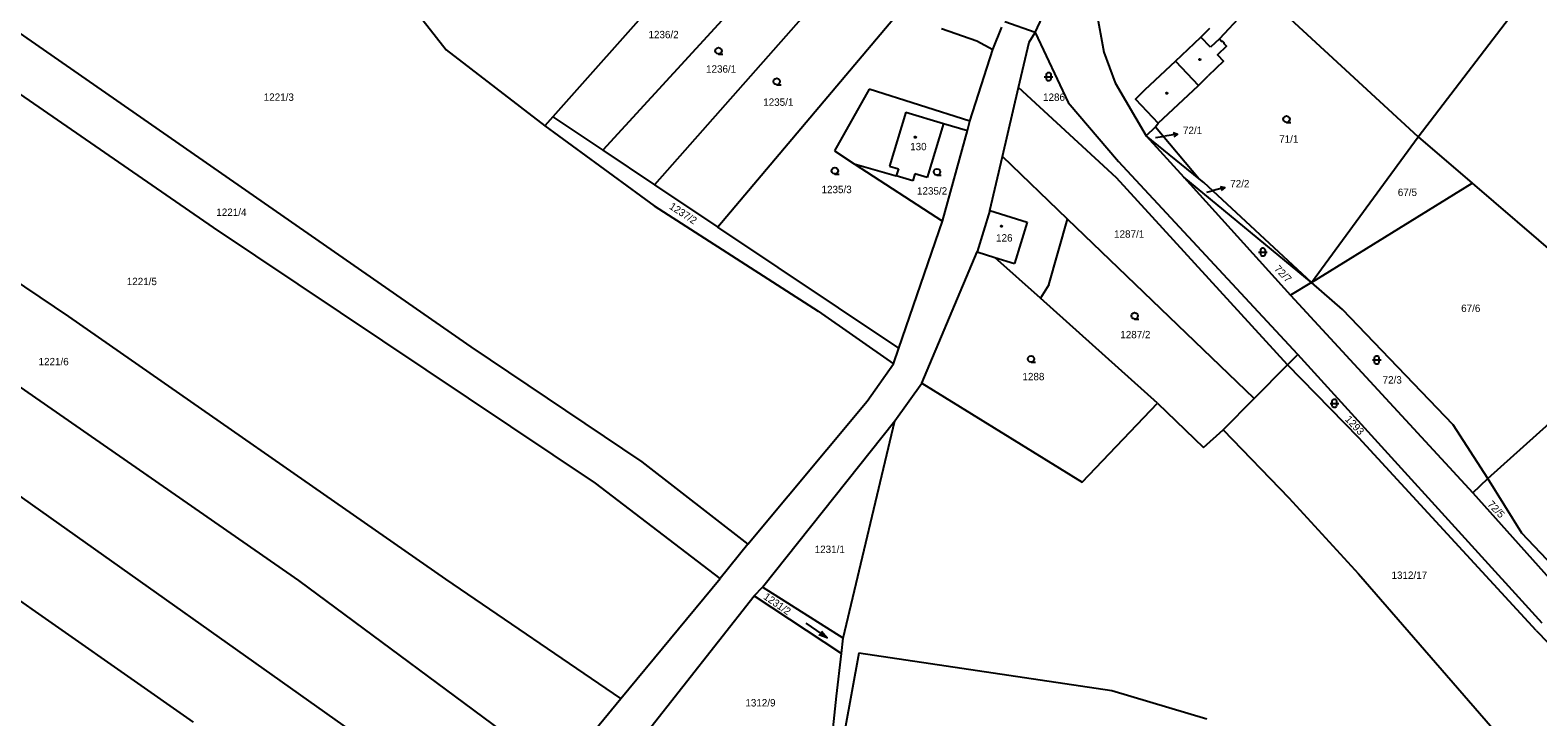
# Model space of a CAD drawing. Extents: x -799786 to -795190, y -1021716 to -1017834.
# Drawn here: x -798278.5 to -797930.9, y -1019350.1 to -1019191.9 of the extents above; entities that cross this region are included whole.
import ezdxf

# ---------------------------------------------------------------- set-up
doc = ezdxf.new("R2010")
doc.units = 0
for name, color, linetype in [('Default', 7, 'Continuous'), ('KN_HRANICE', 7, 'Continuous'), ('KN_KULTURY', 7, 'Continuous'), ('KN_PARCELY', 7, 'Continuous'), ('KN_SLUCKY', 7, 'Continuous')]:
    doc.layers.add(name, color=color, linetype=linetype)

# ---------------------------------------------------------------- blocks, each defined once
blk = doc.blocks.new('304')
at = {"layer": 'Default'}
blk.add_lwpolyline([(0, 0), (-0.38, 0.1), (-0.65, 0.37), (-0.75, 0.74), (-0.65, 1.11), (-0.38, 1.38), (-0.01, 1.48), (0.36, 1.38), (0.63, 1.11), (0.73, 0.73), (0.63, 0.35), (0.36, 0.08), (-0.02, -0.02), (0.98, -0.02)], dxfattribs=at)
blk = doc.blocks.new('316')
at = {"layer": 'Default'}
for points in [[(-1, 1), (0.27, 1), (1, 1)], [(-0.5, 1.5), (-0.4, 1.79), (-0.15, 1.97), (0.16, 1.97), (0.41, 1.79), (0.51, 1.5), (0.51, 0.5), (0.41, 0.21), (0.16, 0.03), (-0.15, 0.03), (-0.4, 0.21), (-0.5, 0.5), (-0.5, 1.5)]]:
    blk.add_lwpolyline(points, dxfattribs=at)
blk = doc.blocks.new('802')
at = {"layer": 'Default'}
blk.add_line((-3, 0), (3, 0), dxfattribs=at)
blk.add_lwpolyline([(1, 0.5), (3, 0), (1, -0.5)], dxfattribs=at)
blk = doc.blocks.new('10292')
at = {"layer": 'Default'}
blk.add_line((0, 3), (0, 0), dxfattribs=at)
blk.add_lwpolyline([(-0.5, 2), (0, 3), (0.5, 2)], dxfattribs=at)
blk = doc.blocks.new('402')
at = {"layer": 'Default'}
blk.add_lwpolyline([(0.09, 0.15), (0.18, 0), (0.09, -0.15), (-0.09, -0.15), (-0.18, 0), (-0.09, 0.15), (0.09, 0.15)], dxfattribs=at)

msp = doc.modelspace()

# ---------------------------------------------------------------- linework, layer by layer
at = {"layer": 'KN_HRANICE'}
for p, q in [((-798347.52, -1019146.35), (-798176.91, -1019264.88)), ((-797958.45, -1019216.47), (-797917.67, -1019163.19)), ((-798119.98, -1019168.95), (-798158.02, -1019211.88)), ((-798106.25, -1019175.74), (-798146.5, -1019219.57)), ((-798046.82, -1019192.47), (-798040.29, -1019178.61)), ((-798093.94, -1019181.55), (-798134.55, -1019227.54)), ((-798190.13, -1019186.83), (-798182.57, -1019196.42)), ((-798078.38, -1019188.04), (-798119.93, -1019237.3)), ((-798032.69, -1019187.31), (-798030.99, -1019196.93)), ((-797999, -1019188.24), (-798004.3, -1019193.91)), ((-797958.45, -1019216.47), (-797988.89, -1019188.44)), ((-798068.37, -1019191.52), (-798060.24, -1019194.35)), ((-798056.57, -1019196.32), (-798054.49, -1019191.2)), ((-798046.82, -1019192.47), (-798053.76, -1019189.97)), ((-798048.16, -1019194.68), (-798046.82, -1019192.47)), ((-798046.82, -1019192.47), (-798039.2, -1019208.59)), ((-798008.6, -1019193.51), (-798006.49, -1019191.45)), ((-798060.24, -1019194.35), (-798056.57, -1019196.32)), ((-798050.59, -1019205.12), (-798048.16, -1019194.68)), ((-798006.34, -1019195.81), (-798008.6, -1019193.51)), ((-798004.3, -1019193.91), (-798006.34, -1019195.81)), ((-798269.58, -1019257.87), (-798358.17, -1019198.54)), ((-798236.26, -1019237.37), (-798295.35, -1019196.67)), ((-798182.57, -1019196.42), (-798159.84, -1019213.93)), ((-798061.82, -1019212.89), (-798056.57, -1019196.32)), ((-798030.99, -1019196.93), (-798028.35, -1019204)), ((-798009.16, -1019204.63), (-798006.89, -1019202.42)), ((-798085.07, -1019205.49), (-798093.09, -1019219.72)), ((-798061.82, -1019212.89), (-798085.07, -1019205.49)), ((-798054.32, -1019221.03), (-798050.59, -1019205.12)), ((-798028.06, -1019225.96), (-798050.59, -1019205.12)), ((-798028.35, -1019204), (-798021.19, -1019216.24)), ((-798018.42, -1019213.3), (-798009.16, -1019204.63)), ((-798039.2, -1019208.59), (-798027.56, -1019222.16)), ((-798158.02, -1019211.88), (-798159.84, -1019213.93)), ((-798158.02, -1019211.88), (-798146.5, -1019219.57)), ((-798067.95, -1019213.37), (-798071.72, -1019225.83)), ((-798067.95, -1019213.37), (-798062.4, -1019215)), ((-798062.4, -1019215), (-798061.82, -1019212.89)), ((-798019.05, -1019214.21), (-798018.42, -1019213.3)), ((-798159.84, -1019213.93), (-798134.6, -1019232.4)), ((-798068.14, -1019235.94), (-798062.4, -1019215)), ((-798021.19, -1019216.24), (-798019.05, -1019214.21)), ((-798021.19, -1019216.24), (-798012.54, -1019225.79)), ((-798008.94, -1019226.16), (-798021.19, -1019216.24)), ((-798019.05, -1019214.21), (-798008.94, -1019226.16)), ((-797983.09, -1019250.06), (-797958.45, -1019216.47)), ((-797958.45, -1019216.47), (-797946.01, -1019227.17)), ((-798146.5, -1019219.57), (-798134.55, -1019227.54)), ((-798093.09, -1019219.72), (-798088.51, -1019222.7)), ((-798088.51, -1019222.7), (-798068.14, -1019235.94)), ((-798088.51, -1019222.7), (-798078.8, -1019225.46)), ((-798057.23, -1019233.47), (-798054.32, -1019221.03)), ((-798039.31, -1019235.46), (-798054.32, -1019221.03)), ((-797986.2, -1019266.62), (-798027.56, -1019222.16)), ((-798134.55, -1019227.54), (-798119.93, -1019237.3)), ((-798074.98, -1019226.61), (-798078.8, -1019225.46)), ((-798074.5, -1019224.99), (-798074.98, -1019226.61)), ((-798071.72, -1019225.83), (-798074.5, -1019224.99)), ((-797988.61, -1019269.05), (-798028.06, -1019225.96)), ((-798012.54, -1019225.79), (-797987.94, -1019252.98)), ((-797983.09, -1019250.06), (-798012.54, -1019225.79)), ((-798007.89, -1019227.01), (-798008.94, -1019226.16)), ((-797983.09, -1019250.06), (-798007.89, -1019227.01)), ((-797983.09, -1019250.06), (-797946.01, -1019227.17)), ((-797946.01, -1019227.17), (-797925.82, -1019244.54)), ((-798134.6, -1019232.4), (-798096.79, -1019256.67)), ((-798057.23, -1019233.47), (-798060.19, -1019242.98)), ((-798148.19, -1019296.29), (-798236.26, -1019237.37)), ((-798078.19, -1019265.16), (-798119.93, -1019237.3)), ((-798078.19, -1019265.16), (-798068.14, -1019235.94)), ((-798043.66, -1019250.61), (-798039.31, -1019235.46)), ((-797996.29, -1019276.8), (-798039.31, -1019235.46)), ((-798323.08, -1019244.85), (-798216.61, -1019318.7)), ((-798072.89, -1019273.22), (-798060.19, -1019242.98)), ((-798060.19, -1019242.98), (-798056.11, -1019244.26)), ((-798045.59, -1019253.66), (-798056.11, -1019244.26)), ((-798385.05, -1019250.48), (-798240.9, -1019351.36)), ((-798043.66, -1019250.61), (-798045.59, -1019253.66)), ((-797983.09, -1019250.06), (-797987.94, -1019252.98)), ((-797975.96, -1019256.3), (-797983.09, -1019250.06)), ((-798018.55, -1019277.83), (-798045.59, -1019253.66)), ((-797987.94, -1019252.98), (-797945.88, -1019298.52)), ((-798182.69, -1019318.4), (-798269.58, -1019257.87)), ((-798096.79, -1019256.67), (-798079.43, -1019268.77)), ((-797950.44, -1019282.82), (-797975.96, -1019256.3)), ((-797942.42, -1019295.21), (-797904.34, -1019261.03)), ((-798176.91, -1019264.88), (-798137.44, -1019291.33)), ((-798079.43, -1019268.77), (-798078.19, -1019265.16)), ((-798085.54, -1019277.41), (-798079.43, -1019268.77)), ((-797996.29, -1019276.8), (-797988.61, -1019269.05)), ((-797988.61, -1019269.05), (-797986.2, -1019266.62)), ((-797972.19, -1019285.87), (-797988.61, -1019269.05)), ((-797929.91, -1019328.57), (-797986.2, -1019266.62)), ((-798079.13, -1019281.89), (-798072.89, -1019273.22)), ((-798072.89, -1019273.22), (-798035.91, -1019296.09)), ((-798113.01, -1019310.31), (-798085.54, -1019277.41)), ((-798035.91, -1019296.09), (-798018.55, -1019277.83)), ((-798018.55, -1019277.83), (-798007.94, -1019288.03)), ((-798003.42, -1019284), (-797996.29, -1019276.8)), ((-798109.65, -1019320.22), (-798079.13, -1019281.89)), ((-798091.06, -1019331.99), (-798079.13, -1019281.89)), ((-797942.42, -1019295.21), (-797950.44, -1019282.82)), ((-798007.94, -1019288.03), (-798003.42, -1019284)), ((-798003.42, -1019284), (-797988.26, -1019299.67)), ((-797931.25, -1019330.22), (-797972.19, -1019285.87)), ((-798172.28, -1019376.09), (-798295.38, -1019289)), ((-798137.44, -1019291.33), (-798113.01, -1019310.31)), ((-798119.41, -1019318.24), (-798148.19, -1019296.29)), ((-797945.88, -1019298.52), (-797942.42, -1019295.21)), ((-797934.55, -1019307.78), (-797942.42, -1019295.21)), ((-797988.26, -1019299.67), (-797972.22, -1019317.2)), ((-797945.88, -1019298.52), (-797920.03, -1019327.44)), ((-798113.01, -1019310.31), (-798119.41, -1019318.24)), ((-797910.64, -1019333.1), (-797934.55, -1019307.78)), ((-797972.22, -1019317.2), (-797940.25, -1019353.95)), ((-798216.61, -1019318.7), (-798156.56, -1019363.16)), ((-798142.29, -1019345.88), (-798182.69, -1019318.4)), ((-798142.29, -1019345.88), (-798119.41, -1019318.24)), ((-798111.54, -1019322.28), (-798109.65, -1019320.22)), ((-798091.06, -1019331.99), (-798109.65, -1019320.22)), ((-798136.21, -1019353.6), (-798111.54, -1019322.28)), ((-798111.54, -1019322.28), (-798091.47, -1019335.52)), ((-797931.25, -1019330.22), (-797925.69, -1019335.98)), ((-798091.47, -1019335.52), (-798091.06, -1019331.99)), ((-798092.62, -1019345.38), (-798091.47, -1019335.52)), ((-798087.44, -1019335.46), (-798090.65, -1019353.16)), ((-798029.12, -1019344.11), (-798087.44, -1019335.46)), ((-798093.69, -1019355.58), (-798092.62, -1019345.38)), ((-798007.2, -1019350.68), (-798029.12, -1019344.11)), ((-798156.56, -1019363.16), (-798142.29, -1019345.88))]:
    msp.add_line(p, q, dxfattribs=at)
msp.add_lwpolyline([(-798004.3, -1019193.91), (-798003.71, -1019194.53), (-798003.59, -1019194.44), (-798003.18, -1019194.85), (-798003.28, -1019194.96), (-798002.7, -1019195.61), (-798004.71, -1019197.57), (-798003.35, -1019199.07), (-798006.89, -1019202.42)], dxfattribs=at)
at = {"layer": 'KN_PARCELY'}
for p, q in [((-798019.06, -1019216.65), (-798016.9, -1019216.3)), ((-798007.19, -1019229.22), (-798005.95, -1019228.89))]:
    msp.add_line(p, q, dxfattribs=at)
at = {"layer": 'KN_SLUCKY'}
for p, q in [((-798014.45, -1019199.03), (-798008.6, -1019193.51)), ((-798014.45, -1019199.03), (-798021.54, -1019205.73)), ((-798014.45, -1019199.03), (-798009.16, -1019204.63)), ((-798076.6, -1019210.76), (-798080.37, -1019223.22)), ((-798076.6, -1019210.76), (-798067.95, -1019213.37)), ((-798080.37, -1019223.22), (-798078.31, -1019223.84)), ((-798078.31, -1019223.84), (-798078.8, -1019225.46)), ((-798057.23, -1019233.47), (-798048.6, -1019236.17)), ((-798048.6, -1019236.17), (-798051.56, -1019245.68)), ((-798056.11, -1019244.26), (-798051.56, -1019245.68))]:
    msp.add_line(p, q, dxfattribs=at)
msp.add_lwpolyline([(-798021.54, -1019205.73), (-798023.68, -1019207.76), (-798018.42, -1019213.3)], dxfattribs=at)

# ---------------------------------------------------------------- block references
at = {"layer": 'KN_KULTURY'}
for name, p in [('304', (-798119.79, -1019197.39)), ('402', (-798008.83, -1019198.63)), ('304', (-798106.36, -1019204.46)), ('316', (-798043.69, -1019203.64)), ('402', (-798016.41, -1019206.4)), ('304', (-797988.83, -1019213.14)), ('402', (-798074.41, -1019216.56)), ('304', (-798092.97, -1019225.03)), ('304', (-798069.43, -1019225.3)), ('402', (-798054.56, -1019237.08)), ('316', (-797994.28, -1019244.04)), ('304', (-798023.84, -1019258.47)), ('304', (-798047.72, -1019268.4)), ('316', (-797968.04, -1019268.9)), ('316', (-797977.79, -1019278.9))]:
    msp.add_blockref(name, p, dxfattribs=at)
at = {"layer": 'KN_KULTURY', "rotation": -34.559972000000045}
msp.add_blockref('802', (-798097.18, -1019330.25), dxfattribs=at)
at = {"layer": 'KN_PARCELY'}
for p, rotation in [((-798016.9, -1019216.3), -80.91225800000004), ((-798005.95, -1019228.89), -75.12538399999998)]:
    msp.add_blockref('10292', p, dxfattribs=dict(at, rotation=rotation))

# ---------------------------------------------------------------- texts
for s, height, p in [('1236/2', 1.7, (-798135.94, -1019193.76)), ('1236/1', 1.7, (-798122.67, -1019201.69)), ('1221/3', 1.7, (-798224.66, -1019208.18)), ('1286', 1.7, (-798044.97, -1019208.19)), ('1235/1', 1.7, (-798109.49, -1019209.33)), ('72/1', 0.1, (-798019.05, -1019216.65)), ('72/1', 1.7, (-798012.7, -1019215.83)), ('71/1', 1.7, (-797990.52, -1019217.82)), ('130', 1.7, (-798075.61, -1019219.57)), ('72/2', 1.7, (-798001.81, -1019228.12)), ('1235/3', 1.7, (-798096.04, -1019229.46)), ('1235/2', 1.7, (-798074.03, -1019229.79)), ('72/2', 0.1, (-798007.18, -1019229.22)), ('67/5', 1.7, (-797963.17, -1019230.11)), ('1221/4', 1.7, (-798235.59, -1019234.7)), ('1287/1', 1.7, (-798028.59, -1019239.72)), ('126', 1.7, (-798055.8, -1019240.61)), ('1221/5', 1.7, (-798256.24, -1019250.65)), ('67/6', 1.7, (-797948.56, -1019256.84)), ('1287/2', 1.7, (-798027.16, -1019262.9)), ('1221/6', 1.7, (-798276.58, -1019269.12)), ('1288', 1.7, (-798049.71, -1019272.57)), ('72/3', 1.7, (-797966.67, -1019273.33)), ('1231/1', 1.7, (-798097.62, -1019312.37)), ('1312/17', 1.7, (-797964.62, -1019318.34)), ('1312/9', 1.7, (-798113.6, -1019347.74))]:
    msp.add_text(s, height=height, dxfattribs=at).set_placement(p)
for s, rotation, p in [('1237/2', 326.758, (-798131.31, -1019232.91)), ('72/7', 314.095, (-797991.77, -1019247.04)), ('1293', 313.293, (-797975.46, -1019281.69)), ('72/5', 313.752, (-797942.62, -1019301.29)), ('1231/2', 325.325, (-798109.59, -1019322.82))]:
    msp.add_text(s, height=1.7, rotation=rotation, dxfattribs=at).set_placement(p)

doc.saveas('drawing.dxf')
